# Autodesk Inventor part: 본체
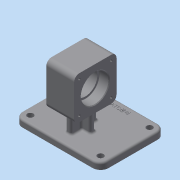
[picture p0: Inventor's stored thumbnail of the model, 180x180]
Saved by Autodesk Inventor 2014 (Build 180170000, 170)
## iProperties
Created: 2020-11
Part Number: 본체
Material: Generic
Document SubType Name: Modeling
Designer: kh
Density: 1 g/cm^3
Appearance: Default
Author: kh
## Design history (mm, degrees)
sketch "Sketch1"
  geometry: L1 (-65, -49)-(65, -49); L2 (65, -49)-(65, 49); L3 (65, 49)-(-65, 49); L4 (-65, 49)-(-65, -49); L5 (-65, -49)-(65, 49); L6 (65, -49)-(-65, 49); 1 further point
  constraints: 12 end point, 2 midpoint, 2 parallel, 1 horizontal, 1 perpendicular
  dimensions: "d0" = 130 distance of L2.end L3.end; "d1" = 98 distance of L1.end L2.end
extrude "Extrusion1" new body sketch "Sketch1" distance "d2" = 10; taper "d3" = 0 deg
workplane "Work Plane1"
sketch "Sketch2"
  geometry: L1 (44, -102)-(86, -102); L2 (86, -102)-(86, -38); L3 (86, -38)-(44, -38); L4 (44, -38)-(44, -102); L5 (130, 0)-(130, -10) reference; L6 (130, 0)-(0, 0) reference; 2 further points
  constraints: 8 end point, 2 parallel, 1 horizontal, 1 midpoint, 1 perpendicular, 1 vertical alignment
  dimensions: "d6" = 42 distance of L1.start L1.end; "d7" = 64 distance of L1.end L2.end; "d8" = 38 distance between parallel lines of L3 L6
extrude "Extrusion2" join sketch "Sketch2" stored distance "d9" = 64; taper "d10" = 0 deg
sketch "Sketch4"
  geometry: L1 (61, -38)-(61, -10); L2 (69, -38)-(69, -10); L3 (69, -10)-(61, -10); L4 (61, -38)-(69, -38); L5 (130, -10)-(0, -10) reference; L6 (86, -38)-(44, -38) reference; 2 further points
  constraints: 8 end point, 2 collinear, 2 parallel, 1 midpoint, 1 perpendicular, 1 vertical, 1 vertical alignment
  dimensions: "d11" = 8 distance of L1.start L2.start
extrude "Extrusion3" join sketch "Sketch4" stored distance "d12" = 40; taper "d13" = 0 deg
workplane "Work Plane3"
sketch "Sketch5"
  geometry: L1 (48, 38)-(48, 10); L2 (48, 10)-(82, 10); L3 (82, 10)-(82, 38); L4 (82, 38)-(48, 38); L5 (130, 10)-(0, 10) reference; L6 (86, 38)-(44, 38) reference; 2 further points
  constraints: 8 end point, 2 collinear, 2 parallel, 1 midpoint, 1 perpendicular, 1 vertical, 1 vertical alignment
  dimensions: "d14" = 34 distance of L1.end L2.end
extrude "Extrusion4" join sketch "Sketch5" stored distance "d15" = 8; taper "d16" = 0 deg
fillet "Fillet1" dims "d17" = 8
sketch "Sketch6"
  geometry: L1 (0, 48)-(0, 0) reference; L2 (-56, 56)-(-8, 56) reference; C1 r 21 at (-32, 24); 3 further points
  constraints: 2 midpoint, 1 centre point, 1 horizontal alignment, 1 vertical alignment
  dimensions: "d18" = 42 diameter of C1
extrude "Extrusion5" cut sketch "Sketch6" distance "d19" = 15; taper "d20" = 0 deg
sketch "Sketch7"
  geometry: C1 r 21 at (-32, 24) reference; 1 further point
hole "Hole1" sketch "Sketch7" at (-32, 24) diameter "d21" = 36; stored, may be unused: countersink angle "d25" = 90 deg, drill point angle "d27" = 118 deg; dims "d22" = 6, "d23" = 42, "d24" = 15, "d26" = 8
fillet "Fillet2" dims "d28" = 12
hole "Hole2" diameter "d31" = 9; stored, may be unused: countersink angle "d35" = 90 deg, drill point angle "d37" = 118 deg; dims "d29" = 10, "d30" = 10, "d32" = 6, "d33" = 42, "d34" = 15, "d36" = 8
pattern_linear "Rectangular Pattern1"
fillet "Fillet3" dims "d42" = 0.3
hole "Hole3" diameter "d45" = 3.242; stored, may be unused: countersink angle "d49" = 90 deg, drill point angle "d51" = 118 deg; dims "d43" = 10, "d44" = 10, "d46" = 8, "d47" = 42, "d48" = 15, "d50" = 10
pattern_linear "Rectangular Pattern2"
workplane "Work Plane4"
chamfer "Chamfer1" distance "d56" = 1; stored, may be unused: second distance "d57" = 2, angle "d58" = 45 deg
sketch "Sketch9"
  geometry: L1 (65, -37)-(65, 37) reference; L2 (53, 49)-(-53, 49) reference; 2 further points
  constraints: 1 other
  dimensions: "d59" = 65 distance from line of L1 point (0, 39); "d60" = 10 distance from line of L2 point (0, 39)
emboss "Emboss1" sketch "Sketch9" dims "d0" = 130, "d1" = 98, "d61" = 0.5, "d62" = 0
fillet "Fillet4" dims "d63" = 3
fillet "Fillet5" dims "d64" = 3
hole "Hole4" diameter "d67" = 3.242; stored, may be unused: countersink angle "d71" = 90 deg, drill point angle "d73" = 118 deg; dims "d65" = 10, "d66" = 10, "d68" = 8, "d69" = 4, "d70" = 2, "d72" = 10
pattern_linear "Rectangular Pattern3"
body "Solid1"
other parameters: "d4" = -62
